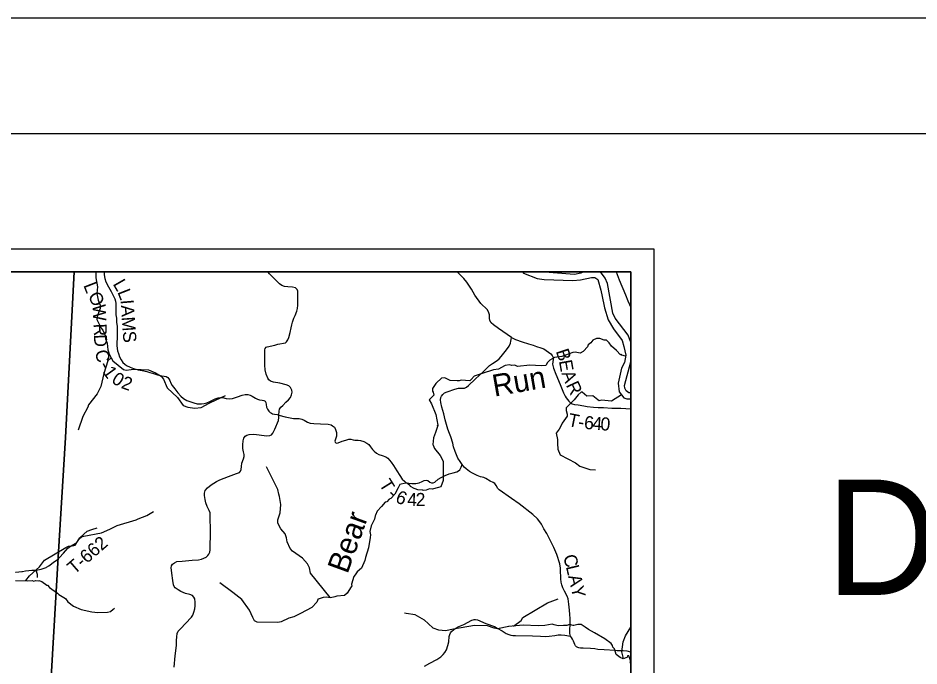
# Model space of a CAD drawing. Extents: x -1.8 to 75.7, y -2 to 25.
# Drawn here: x 47.944 to 51.85, y 20.804 to 23.612 of the extents above; entities that cross this region are included whole.
import ezdxf

# ---------------------------------------------------------------- set-up
doc = ezdxf.new("R2010")
doc.units = 0
for name, color, linetype in [('GM_X_County_Road', 7, 'Continuous'), ('GM_X_County_Road_Text', 7, 'Continuous'), ('GM_X_Major_River', 7, 'Continuous'), ('GM_X_Minor_River', 7, 'Continuous'), ('GM_X_Minor_River_Text', 7, 'Continuous'), ('GM_X_Township', 7, 'Continuous'), ('GM_X_Township_Road', 7, 'Continuous'), ('GM_X_Township_Road_Text', 7, 'Continuous'), ('GM_X_Township_ROW', 7, 'Continuous'), ('SH_Border', 7, 'Continuous'), ('SH_Cut_Line', 7, 'Continuous'), ('SH_Data', 7, 'Continuous'), ('SH_Text', 7, 'Continuous')]:
    doc.layers.add(name, color=color, linetype=linetype)

msp = doc.modelspace()

# ---------------------------------------------------------------- linework, layer by layer
at = {"layer": 'GM_X_County_Road'}
for points in [[(48.3169, 22.5121), (48.3169, 22.5118), (48.318, 22.4997), (48.3204, 22.4834), (48.3253, 22.4689), (48.3357, 22.4478), (48.348, 22.4269), (48.3566, 22.41), (48.363, 22.3958), (48.367, 22.3857), (48.3681, 22.3747), (48.3681, 22.3575), (48.3677, 22.341), (48.368, 22.3276), (48.3682, 22.3261)], [(48.6209, 20.7993), (48.6259, 20.8475), (48.6307, 20.8934), (48.6311, 20.9145), (48.6318, 20.9299), (48.6341, 20.9453), (48.6388, 20.9553), (48.6492, 20.9668), (48.6701, 20.9888), (48.6956, 21.0157), (48.7013, 21.0236), (48.7067, 21.0368), (48.7106, 21.0524), (48.7117, 21.0648), (48.7119, 21.0811), (48.7101, 21.0945), (48.7061, 21.1026), (48.7008, 21.1094), (48.6888, 21.1142), (48.6707, 21.1189), (48.6501, 21.1266), (48.6381, 21.1341), (48.6245, 21.1429), (48.6202, 21.1484), (48.618, 21.1556), (48.6146, 21.1744), (48.6101, 21.207), (48.6092, 21.2195), (48.6085, 21.229), (48.61, 21.2386), (48.6137, 21.2455), (48.6218, 21.2518), (48.632, 21.2564), (48.6549, 21.2586), (48.699, 21.2625), (48.7262, 21.2641), (48.7391, 21.2675), (48.7498, 21.2713), (48.7593, 21.2763), (48.7672, 21.2826), (48.7708, 21.2885), (48.7749, 21.2978), (48.7765, 21.3073), (48.7769, 21.3175), (48.7769, 21.3365), (48.7787, 21.361), (48.779, 21.3825), (48.7778, 21.4051), (48.7767, 21.4348), (48.7776, 21.4545), (48.7765, 21.4676), (48.7733, 21.4785), (48.7642, 21.4959), (48.7584, 21.5115), (48.7548, 21.5258), (48.7525, 21.5432), (48.7518, 21.5537), (48.755, 21.5647), (48.7647, 21.5761), (48.7819, 21.5892), (48.805, 21.6041), (48.8195, 21.6112), (48.8568, 21.6257), (48.8906, 21.6388), (48.9042, 21.6426), (48.9089, 21.649), (48.9112, 21.6562), (48.9123, 21.6691), (48.9148, 21.6834), (48.9214, 21.702), (48.9239, 21.7126), (48.9239, 21.721), (48.9216, 21.7327), (48.9193, 21.7459), (48.9189, 21.7629), (48.9196, 21.7803), (48.9223, 21.7914), (48.9282, 21.8002), (48.9352, 21.8041), (48.9463, 21.8072), (48.966, 21.8081), (49.023, 21.802), (49.0357, 21.8025), (49.0425, 21.8059), (49.0493, 21.8133), (49.058, 21.8301), (49.0725, 21.8684), (49.0747, 21.8803), (49.0744, 21.8912), (49.0757, 21.908), (49.0781, 21.9172), (49.0834, 21.9252), (49.0917, 21.9332), (49.1055, 21.9468), (49.1169, 21.9579), (49.1247, 21.9679), (49.13, 21.9785), (49.1322, 21.9904), (49.131, 22.0001), (49.1256, 22.0112), (49.1179, 22.0183), (49.1065, 22.0229), (49.0788, 22.029), (49.0514, 22.0338), (49.0388, 22.0387), (49.031, 22.044), (49.0264, 22.052), (49.0196, 22.0683), (49.0153, 22.087), (49.0142, 22.1083), (49.0136, 22.1418), (49.0136, 22.1646), (49.0136, 22.1738), (49.0157, 22.1796), (49.0196, 22.1852), (49.0245, 22.1874), (49.0567, 22.1942), (49.0703, 22.1988), (49.1033, 22.2051), (49.1082, 22.2092), (49.1133, 22.2174), (49.1181, 22.2281), (49.1234, 22.249), (49.1283, 22.2691), (49.1312, 22.2822), (49.1341, 22.2941), (49.1397, 22.3111), (49.1448, 22.3225), (49.153, 22.3411), (49.1557, 22.354), (49.1574, 22.3678), (49.1576, 22.3875), (49.1576, 22.4173), (49.1567, 22.4287), (49.1535, 22.436), (49.147, 22.443), (49.1341, 22.4457), (49.1133, 22.4474), (49.0987, 22.4486), (49.0875, 22.4534), (49.0776, 22.4605), (49.057, 22.4811), (49.0337, 22.5029), (49.0263, 22.5121)], [(50.313, 21.1285), (50.3057, 21.1432), (50.3016, 21.1562), (50.2992, 21.1671), (50.2976, 21.1819), (50.297, 21.1938), (50.2963, 21.211), (50.2963, 21.2279), (50.2932, 21.2472), (50.2806, 21.2868), (50.2672, 21.3177), (50.2547, 21.3435), (50.2459, 21.3613), (50.236, 21.3782), (50.2237, 21.3983), (50.2135, 21.418), (50.2067, 21.4293), (50.1967, 21.4418), (50.1758, 21.4604), (50.1164, 21.5067), (50.0831, 21.5305), (50.0305, 21.5672), (50.0236, 21.5739), (50.0169, 21.5864), (50.0111, 21.5944), (50.0033, 21.5994), (49.9915, 21.6053), (49.9727, 21.6159), (49.963, 21.6205), (49.9491, 21.6245), (49.9341, 21.6301), (49.9142, 21.6396), (49.9017, 21.6475), (49.8872, 21.6586), (49.8788, 21.6664), (49.87, 21.6772), (49.8614, 21.6902), (49.8511, 21.7053), (49.8446, 21.719), (49.8392, 21.7339), (49.832, 21.7538), (49.8297, 21.7704), (49.8208, 21.7968), (49.8147, 21.8111), (49.8078, 21.8299), (49.7955, 21.8714), (49.7897, 21.8974), (49.7819, 21.925), (49.7769, 21.9454), (49.7763, 21.9571), (49.7773, 21.967), (49.7797, 21.9733), (49.7856, 21.9813), (49.7925, 21.9875), (49.8052, 21.9925), (49.8374, 22.0031), (49.8535, 22.0074), (49.8686, 22.0074), (49.879, 22.0087), (49.888, 22.0122), (49.8965, 22.0191), (49.9253, 22.0464), (49.9637, 22.0823), (49.9758, 22.0941), (49.988, 22.1065), (50.0012, 22.1149), (50.0206, 22.1285), (50.0293, 22.135), (50.039, 22.1456), (50.0615, 22.1735), (50.0734, 22.1906), (50.0794, 22.2025), (50.0812, 22.2118), (50.0816, 22.2187), (50.0831, 22.2269), (50.0265, 22.266), (50.0059, 22.2818), (49.9948, 22.2915), (49.99, 22.302), (49.9883, 22.3108), (49.988, 22.3264), (49.9837, 22.3389), (49.9776, 22.3487), (49.9505, 22.3753), (49.9249, 22.4108), (49.9093, 22.4374), (49.8903, 22.4676), (49.8761, 22.4838), (49.8494, 22.5102), (49.8464, 22.5121)], [(50.5376, 22.5121), (50.5503, 22.4781), (50.577, 22.4131), (50.5878, 22.3872), (50.6002, 22.3575)], [(48.3682, 22.3261), (48.3703, 22.3108), (48.3715, 22.2941), (48.3732, 22.2752), (48.3739, 22.2582), (48.3741, 22.2393), (48.3736, 22.2237), (48.3727, 22.2067), (48.3727, 22.1926), (48.3739, 22.1806), (48.3758, 22.1697), (48.3791, 22.1586), (48.3845, 22.1442), (48.3911, 22.1312), (48.3984, 22.1197), (48.4064, 22.1121), (48.4147, 22.1064), (48.4296, 22.0987), (48.4452, 22.093), (48.465, 22.088), (48.482, 22.0847), (48.502, 22.08), (48.5148, 22.0765), (48.5273, 22.0732), (48.5355, 22.0706), (48.548, 22.0659), (48.5596, 22.0628), (48.5676, 22.0611), (48.578, 22.0607), (48.5865, 22.0583), (48.5934, 22.0536), (48.5976, 22.0486), (48.6019, 22.0406), (48.607, 22.029), (48.6122, 22.0198), (48.6238, 22.0047), (48.6368, 21.988), (48.6498, 21.9736), (48.662, 21.9634), (48.6764, 21.9547), (48.7066, 21.9438), (48.721, 21.9398), (48.739, 21.9396), (48.7515, 21.9415), (48.7628, 21.945), (48.7756, 21.9502), (48.7987, 21.9618), (48.8114, 21.9665), (48.8216, 21.9679), (48.8308, 21.9674), (48.8459, 21.9639), (48.861, 21.962), (48.874, 21.9634), (48.895, 21.97), (48.915, 21.9771), (48.9282, 21.9807), (48.9408, 21.9802), (48.9497, 21.9781), (48.9594, 21.9738), (48.9728, 21.9653), (48.9823, 21.9604), (48.991, 21.9578), (49.0021, 21.9566), (49.009, 21.9549), (49.0149, 21.9512), (49.0186, 21.9455), (49.0198, 21.937), (49.0212, 21.9254), (49.0255, 21.9167), (49.0318, 21.9082), (49.0371, 21.9029), (49.0434, 21.899), (49.0473, 21.8973), (49.0565, 21.8956), (49.0679, 21.8939), (49.0744, 21.8912)], [(50.3396, 20.9335), (50.3369, 20.9442), (50.3367, 20.957), (50.3373, 20.9879), (50.3373, 21.0099), (50.3365, 21.027), (50.3344, 21.0461), (50.3321, 21.0725), (50.3311, 21.0842), (50.3286, 21.0955), (50.3241, 21.1066), (50.3131, 21.1283), (50.313, 21.1285)], [(50.6002, 20.864), (50.5856, 20.8677), (50.5674, 20.8693), (50.5419, 20.8704), (50.5325, 20.8709), (50.4847, 20.8735), (50.458, 20.876), (50.4449, 20.8777), (50.4261, 20.8796), (50.3937, 20.8816), (50.3828, 20.8819), (50.3752, 20.8825), (50.3705, 20.8841), (50.3654, 20.887), (50.3604, 20.8918), (50.3574, 20.8979), (50.352, 20.9113), (50.3481, 20.9197), (50.343, 20.9273), (50.3396, 20.9335)]]:
    msp.add_lwpolyline(points, dxfattribs=at)
at = {"layer": 'GM_X_Major_River'}
msp.add_line((50.5792, 22.1512), (50.5733, 22.119), dxfattribs=at)
for points in [[(50.1307, 22.5121), (50.1359, 22.5067), (50.195, 22.4832), (50.2245, 22.4788), (50.3494, 22.4742)], [(50.3966, 22.5121), (50.3836, 22.5071), (50.3564, 22.5001), (50.2637, 22.5075), (50.2139, 22.5121)], [(50.6002, 22.2099), (50.6, 22.2105), (50.5889, 22.2374), (50.5333, 22.3111), (50.5226, 22.3326), (50.4999, 22.4618), (50.49, 22.4842), (50.474, 22.5061), (50.4641, 22.5121)], [(50.3494, 22.4742), (50.383, 22.4771), (50.4306, 22.488), (50.445, 22.4881), (50.4575, 22.4791), (50.471, 22.4332), (50.4842, 22.3703), (50.4873, 22.3563), (50.5027, 22.3037), (50.5256, 22.2647), (50.5629, 22.2141), (50.5703, 22.1884), (50.5792, 22.1512)], [(50.5733, 22.119), (50.5602, 22.095), (50.5462, 22.0293), (50.5509, 21.9921), (50.57, 21.9664), (50.5828, 21.9612), (50.5957, 21.9617), (50.6002, 21.9621)], [(50.6002, 21.9872), (50.5918, 21.9874), (50.5811, 21.9965), (50.575, 22.0078), (50.5734, 22.0199), (50.6002, 22.1222)]]:
    msp.add_lwpolyline(points, dxfattribs=at)
at = {"layer": 'GM_X_Minor_River'}
for points in [[(48.2818, 22.5121), (48.2811, 22.4867), (48.2885, 22.4466), (48.285, 22.4179), (48.2917, 22.3892), (48.2994, 22.3677), (48.2997, 22.3536), (48.2878, 22.3236), (48.2861, 22.305), (48.3043, 22.2676), (48.3112, 22.2594), (48.3229, 22.234), (48.3229, 22.2218), (48.3303, 22.2026), (48.3332, 22.1737), (48.3381, 22.1614), (48.3391, 22.1553), (48.3552, 22.1263), (48.4017, 22.0883), (48.4129, 22.0857), (48.4338, 22.0884), (48.4475, 22.091), (48.5097, 22.0871), (48.5396, 22.0752), (48.5645, 22.0603), (48.5739, 22.0464), (48.5901, 22.009), (48.6346, 21.967), (48.6593, 21.9335), (48.6806, 21.9252), (48.7111, 21.9208), (48.7384, 21.9245), (48.773, 21.9432), (48.7784, 21.9464), (48.8432, 21.9762)], [(50.5782, 22.1461), (50.5617, 22.1509), (50.5583, 22.1547), (50.5564, 22.1528), (50.5386, 22.1714), (50.5174, 22.1899), (50.5065, 22.2051), (50.4959, 22.2157), (50.4845, 22.2157), (50.466, 22.2233), (50.4524, 22.2228), (50.4365, 22.2156), (50.4271, 22.2045), (50.4154, 22.1958), (50.4131, 22.1874), (50.3957, 22.1691), (50.3942, 22.1672), (50.3806, 22.16), (50.3598, 22.1637), (50.3492, 22.1622), (50.3012, 22.1457), (50.2699, 22.1403), (50.2498, 22.13), (50.2389, 22.1186), (50.2321, 22.1057), (50.2117, 22.1052), (50.1633, 22.1074), (50.11, 22.1019), (50.0983, 22.1076), (50.0843, 22.1068), (50.0752, 22.1095), (50.0559, 22.106), (50.0525, 22.1052), (50.0268, 22.0907), (50.0061, 22.0873), (49.9562, 22.0719), (49.921, 22.0601), (49.9089, 22.046), (49.9033, 22.0399), (49.8655, 22.0432), (49.8564, 22.0394), (49.8477, 22.0401), (49.8175, 22.0412), (49.794, 22.0526), (49.7796, 22.0518), (49.7574, 22.0304), (49.7547, 22.0289), (49.7408, 22.0068), (49.7411, 21.9954), (49.7442, 21.9913), (49.7461, 21.9776), (49.7264, 21.957), (49.7359, 21.9399), (49.7548, 21.8944), (49.764, 21.8484), (49.7606, 21.8446), (49.764, 21.8457), (49.7545, 21.8153), (49.7455, 21.7928), (49.7429, 21.7636), (49.7433, 21.7613), (49.7497, 21.7461), (49.7739, 21.7169), (49.7868, 21.6922), (49.7868, 21.6675), (49.7865, 21.6185), (49.7872, 21.6075), (49.7771, 21.5804), (49.7676, 21.577), (49.7393, 21.5709), (49.7276, 21.5716), (49.7128, 21.5666), (49.7003, 21.5639), (49.6988, 21.5666), (49.6777, 21.5673), (49.6659, 21.5722), (49.661, 21.5726), (49.6451, 21.5813), (49.6448, 21.5851), (49.6323, 21.5949), (49.6236, 21.5968), (49.5998, 21.5899), (49.5915, 21.5762), (49.5779, 21.5484), (49.5601, 21.5302), (49.5537, 21.5275), (49.5424, 21.5157), (49.5359, 21.5138), (49.5193, 21.4955), (49.5016, 21.4745), (49.4933, 21.457), (49.4925, 21.4547), (49.4895, 21.4407), (49.4744, 21.4117), (49.4699, 21.387), (49.4726, 21.373), (49.4711, 21.3604), (49.4632, 21.3163), (49.45, 21.2748), (49.4477, 21.2608), (49.433, 21.2284)], [(48.3461, 22.1387), (48.3336, 22.1266), (48.3153, 22.071), (48.303, 22.0148), (48.287, 21.9841), (48.2493, 21.9364), (48.247, 21.9258), (48.2243, 21.8851), (48.2043, 21.8262)], [(50.5608, 21.9788), (50.5169, 21.9512), (50.474, 21.9564), (50.4633, 21.9537), (50.4581, 21.9569), (50.4356, 21.9747), (50.4106, 21.974), (50.3904, 21.9906), (50.3854, 21.99), (50.3723, 21.9794), (50.3549, 21.9568), (50.321, 21.9229), (50.3203, 21.9119), (50.3255, 21.8947), (50.3241, 21.8871), (50.3035, 21.8567), (50.3011, 21.8514), (50.2906, 21.8309), (50.2765, 21.8135), (50.2828, 21.7855), (50.2827, 21.7677), (50.2838, 21.7437), (50.294, 21.7187), (50.3607, 21.6843), (50.3795, 21.6704), (50.4237, 21.6561), (50.4474, 21.6538)], [(49.2966, 21.1009), (49.2113, 21.2058), (49.2071, 21.2298), (49.1985, 21.2464), (49.1777, 21.271), (49.1344, 21.302), (49.1231, 21.3138), (49.1103, 21.3415), (49.1086, 21.3594), (49.1019, 21.3764), (49.0829, 21.3979), (49.0704, 21.4226), (49.0705, 21.437), (49.0801, 21.4674), (49.0831, 21.5042), (49.0774, 21.5389), (49.075, 21.5493), (49.0707, 21.5695), (49.0247, 21.661), (49.0215, 21.6675)], [(47.9775, 21.1747), (47.9936, 21.1945), (48.0363, 21.2342), (48.0591, 21.2631), (48.1515, 21.3182), (48.1623, 21.3232), (48.1732, 21.3228), (48.1919, 21.3283), (48.209, 21.3551), (48.2198, 21.3643), (48.2294, 21.367), (48.3061, 21.3813), (48.3421, 21.3964), (48.3733, 21.4129), (48.456, 21.438), (48.4652, 21.4411), (48.5019, 21.4559), (48.5312, 21.4732)], [(49.433, 21.2284), (49.4141, 21.2124), (49.4058, 21.1987), (49.3998, 21.1926), (49.3896, 21.1584), (49.3915, 21.1489), (49.3892, 21.1485), (49.3889, 21.1466), (49.3707, 21.1192), (49.3587, 21.11), (49.3265, 21.1073), (49.3171, 21.1031), (49.2986, 21.0996), (49.2793, 21.1026), (49.2664, 21.1007), (49.2449, 21.0942)], [(47.9334, 21.1752), (47.9845, 21.1734), (48.0045, 21.1746), (48.0124, 21.1719), (48.0196, 21.175), (48.031, 21.1727), (48.034, 21.1747), (48.0465, 21.1697), (48.0684, 21.155), (48.0718, 21.1542), (48.0805, 21.1444), (48.1152, 21.1192)], [(49.2456, 21.0944), (49.239, 21.0803), (49.2183, 21.0574), (49.168, 21.0321), (49.1396, 21.017), (49.1186, 21.0112), (49.0845, 20.9949), (49.0708, 20.993), (48.9808, 20.9936), (48.9697, 21.0004), (48.9622, 21.0136), (48.9477, 21.0467), (48.9147, 21.0922), (48.8759, 21.1227), (48.8189, 21.164)], [(48.115, 21.1194), (48.1214, 21.1137), (48.1494, 21.0962), (48.1603, 21.0814), (48.1846, 21.0629), (48.2175, 21.0485), (48.264, 21.0387), (48.29, 21.0361), (48.332, 21.0374), (48.3452, 21.0408), (48.3566, 21.05), (48.36, 21.0526), (48.3626, 21.0553)], [(50.0922, 20.9773), (50.126, 21.0018), (50.1332, 21.0145), (50.2391, 21.078), (50.286, 21.0951)], [(50.0715, 20.9757), (50.0229, 20.9656), (50.0078, 20.9676), (49.9794, 20.978), (49.9224, 20.9798), (49.8316, 20.9634), (49.7966, 20.9558), (49.7679, 20.9597), (49.7433, 20.9685), (49.7227, 20.9889), (49.7065, 21.0027), (49.6652, 21.0253), (49.6261, 21.0318), (49.6202, 21.0324)], [(50.6002, 20.817), (50.5981, 20.8176), (50.5989, 20.8206), (50.5992, 20.8282), (50.5917, 20.8483), (50.5867, 20.8476), (50.5849, 20.843), (50.5834, 20.8403), (50.5679, 20.8353), (50.5539, 20.8414), (50.5372, 20.8543), (50.5296, 20.8782), (50.5221, 20.8858), (50.5217, 20.8923), (50.5149, 20.9017), (50.4884, 20.9211), (50.4434, 20.9483), (50.4169, 20.9616), (50.4033, 20.9722), (50.3851, 20.9836), (50.3715, 20.9835), (50.3541, 20.9789), (50.3515, 20.9797), (50.3352, 20.9834), (50.3235, 20.9792), (50.3088, 20.98), (50.2857, 20.978), (50.2683, 20.9821), (50.2604, 20.9855), (50.2275, 20.979), (50.1984, 20.9786), (50.1337, 20.9807), (50.0709, 20.9756)], [(50.5695, 20.8359), (50.5615, 20.8656), (50.5674, 20.9087), (50.5772, 20.935), (50.6002, 20.9716)]]:
    msp.add_lwpolyline(points, dxfattribs=at)
at = {"layer": 'GM_X_Township'}
for points in [[(48.1876, 22.5121), (43.8002, 22.5121), (43.8002, 18.978)], [(43.8002, 18.978), (44.8356, 18.9224), (45.3865, 18.8952), (46.1197, 18.859), (46.3714, 18.8466), (46.9192, 18.8195), (47.1815, 18.806), (47.9522, 18.7663), (48.0201, 19.5982), (48.0214, 19.6198), (48.0228, 19.6698), (48.0235, 19.6926), (48.0261, 19.7186), (48.0301, 19.7636), (48.0891, 20.7799), (48.1186, 21.2763), (48.1494, 21.7937), (48.1876, 22.5121)], [(48.1876, 22.5121), (48.1494, 21.7937), (48.1186, 21.2763), (48.0891, 20.7799), (48.0301, 19.7636), (48.0261, 19.7186), (48.0235, 19.6926), (48.0228, 19.6698), (48.0214, 19.6198), (48.0201, 19.5982), (47.9522, 18.7663), (48.8964, 18.7242), (49.0051, 18.7193), (50.1896, 18.6602), (50.591, 18.6401), (50.6002, 18.6397)], [(50.6002, 18.6397), (50.6002, 22.5121), (48.1876, 22.5121)]]:
    msp.add_lwpolyline(points, dxfattribs=at)
at = {"layer": 'GM_X_Township_Road'}
for points in [[(50.0831, 22.2269), (50.1004, 22.2194), (50.1302, 22.2088), (50.1566, 22.1999), (50.1767, 22.1938), (50.1923, 22.1891), (50.2109, 22.1822), (50.223, 22.1781), (50.2336, 22.1714), (50.2544, 22.1566), (50.2595, 22.1499), (50.2637, 22.1409), (50.2645, 22.1329), (50.2628, 22.1216), (50.2613, 22.1127), (50.2622, 22.1056), (50.2649, 22.0942), (50.2752, 22.0685), (50.2944, 22.0236), (50.3089, 21.9875), (50.316, 21.9733), (50.3205, 21.9655), (50.3257, 21.9588), (50.332, 21.9516), (50.3378, 21.946), (50.346, 21.9408), (50.3568, 21.9378), (50.3724, 21.9352), (50.3975, 21.9312)], [(50.3975, 21.9312), (50.4122, 21.9289), (50.4393, 21.9263), (50.4593, 21.9246), (50.4818, 21.9237), (50.518, 21.9216), (50.5582, 21.9209), (50.6002, 21.9188)], [(49.0744, 21.8912), (49.1026, 21.8839), (49.138, 21.8769), (49.1632, 21.8759), (49.1749, 21.874), (49.1849, 21.8696), (49.1986, 21.8603), (49.2099, 21.8566), (49.227, 21.8546), (49.2549, 21.8541), (49.2892, 21.8515), (49.301, 21.849), (49.3079, 21.8454), (49.3156, 21.8386), (49.3207, 21.8296), (49.3249, 21.8156), (49.3245, 21.8003), (49.3205, 21.7866), (49.318, 21.7782), (49.3191, 21.7737), (49.3236, 21.77), (49.332, 21.7709), (49.3497, 21.7782), (49.365, 21.7828), (49.3785, 21.7874), (49.3874, 21.7872), (49.3967, 21.7841), (49.4044, 21.7826), (49.4186, 21.783), (49.4294, 21.7815), (49.443, 21.7768), (49.456, 21.77), (49.4642, 21.7644), (49.4724, 21.7536), (49.4808, 21.7429), (49.4879, 21.735), (49.4981, 21.7268), (49.5085, 21.7212), (49.5227, 21.7161), (49.5382, 21.7106), (49.5466, 21.7051), (49.5617, 21.6878), (49.5719, 21.6734), (49.5866, 21.6504), (49.5998, 21.6295), (49.6093, 21.6136), (49.6188, 21.6043), (49.6255, 21.5994), (49.6381, 21.5959), (49.6512, 21.5948), (49.6684, 21.5943), (49.6833, 21.5983), (49.6961, 21.6034), (49.7043, 21.6076), (49.713, 21.6089), (49.7203, 21.6074), (49.7296, 21.6014), (49.7371, 21.5979), (49.7431, 21.5974), (49.7506, 21.6014), (49.7655, 21.6136), (49.7781, 21.6209), (49.7954, 21.6298), (49.8126, 21.6366), (49.8312, 21.6411), (49.8467, 21.6455), (49.8538, 21.6493), (49.8594, 21.6537), (49.8649, 21.6652), (49.87, 21.6772)], [(48.0672, 21.232), (48.0777, 21.2388), (48.1023, 21.2564), (48.1129, 21.2637), (48.1182, 21.2685), (48.1241, 21.274), (48.1414, 21.2933), (48.1598, 21.3142), (48.1721, 21.3231), (48.1947, 21.3362), (48.202, 21.3441), (48.2117, 21.3589), (48.2285, 21.3759), (48.2438, 21.3879), (48.2634, 21.3949), (48.2863, 21.403)], [(47.933, 21.2107), (47.9345, 21.2109), (47.9597, 21.2138)], [(47.9597, 21.2138), (47.9633, 21.2142), (47.9767, 21.2165), (47.9906, 21.2179), (48.0035, 21.2187), (48.0222, 21.2187)], [(48.0222, 21.2187), (48.0448, 21.2235), (48.0657, 21.231), (48.0672, 21.232)], [(49.706, 20.8032), (49.7287, 20.8161), (49.7603, 20.8322), (49.7766, 20.8444), (49.7873, 20.8534), (49.7949, 20.8628), (49.8019, 20.8747), (49.8078, 20.8923), (49.8112, 20.9091), (49.8137, 20.9315), (49.8162, 20.94), (49.8192, 20.948), (49.8235, 20.954), (49.8332, 20.9616), (49.8426, 20.9683), (49.8552, 20.9747), (49.8767, 20.9843), (49.9115, 21.0024), (49.9169, 21.0047), (49.9216, 21.0056), (49.9272, 21.0056), (49.9361, 21.0036), (49.9727, 20.9885), (50.0096, 20.9745), (50.0214, 20.9685), (50.0425, 20.9563), (50.0604, 20.9453), (50.0714, 20.9406), (50.0801, 20.938), (50.0893, 20.9368), (50.1007, 20.9358), (50.1748, 20.9346), (50.2096, 20.9327), (50.2295, 20.9324), (50.2468, 20.9329), (50.2712, 20.9363), (50.2856, 20.9385), (50.2992, 20.9391), (50.3144, 20.9372), (50.3396, 20.9335)]]:
    msp.add_lwpolyline(points, dxfattribs=at)
at = {"layer": 'GM_X_Township_ROW'}
msp.add_lwpolyline([(48.0286, 21.188), (48.028, 21.2008), (48.0222, 21.2187)], dxfattribs=at)
at = {"layer": 'SH_Border'}
msp.add_lwpolyline([(43.2002, 23.1121), (75.2002, 23.1121), (75.2002, 2.1121), (43.2002, 2.1121)], close=True, dxfattribs=at)
at = {"layer": 'SH_Cut_Line'}
msp.add_lwpolyline([(41.7002, 1.6121), (75.7002, 1.6121), (75.7002, 23.6121), (41.7002, 23.6121)], close=True, dxfattribs=at)
at = {"layer": 'SH_Data'}
for p, q in [((43.7002, 22.6121), (50.7002, 22.6121)), ((50.7002, 22.6121), (50.7002, 15.6121)), ((43.8002, 22.5121), (50.6002, 22.5121)), ((43.8002, 22.5121), (50.6002, 22.5121)), ((50.6002, 22.5121), (50.6002, 15.7121)), ((50.6002, 22.5121), (50.6002, 15.7121))]:
    msp.add_line(p, q, dxfattribs=at)

# ---------------------------------------------------------------- texts
at = {"layer": 'GM_X_County_Road_Text'}
for s, rotation, p in [('L', 291.2729, (48.2265, 22.4543)), ('L', 299.8274, (48.3536, 22.4599)), ('O', 298.5018, (48.2452, 22.4076)), ('L', 291.4457, (48.3738, 22.425)), ('I', 274.7828, (48.3884, 22.3897)), ('W', 272.4964, (48.2672, 22.3701)), ('A', 273.1818, (48.3903, 22.3668)), ('M', 273.9872, (48.3931, 22.316)), ('R', 272.303, (48.2708, 22.2868)), ('D', 272.4218, (48.2727, 22.2401)), ('S', 275.1606, (48.3975, 22.2533)), ('C', 282.5703, (48.277, 22.168)), ('-', 296.9471, (48.2924, 22.1078)), ('1', 305.93, (48.3081, 22.0787)), ('0', 327.6164, (48.3456, 22.0344)), ('2', 340.2531, (48.3875, 22.0096)), ('C', 284.8811, (50.3068, 21.2795)), ('L', 283.4116, (50.3187, 21.2347)), ('A', 283.2649, (50.3285, 21.1934)), ('Y', 282.2601, (50.3399, 21.145))]:
    msp.add_text(s, height=0.0568, rotation=rotation, dxfattribs=at).set_placement(p)
at = {"layer": 'GM_X_Minor_River_Text'}
for s, rotation, p in [('Run', 9.9969, (50.0089, 21.9711)), ('Bear', 69.9999, (49.372, 21.1998))]:
    msp.add_text(s, height=0.0947, rotation=rotation, dxfattribs=at).set_placement(p)
at = {"layer": 'GM_X_Township_Road_Text'}
for s, height, rotation, p in [('B', 0.0568, 288.0968, (50.2749, 22.1683)), ('E', 0.0568, 280.0193, (50.2888, 22.126)), ('A', 0.0568, 290.6476, (50.2993, 22.0731)), ('R', 0.0568, 294.8309, (50.3187, 22.0221)), ('T', 0.0568, 348.6048, (50.3252, 21.8447)), ('6', 0.0568, 354.6585, (50.3964, 21.8319)), ('4', 0.0568, 355.9016, (50.4326, 21.8285)), ('0', 0.0568, 356.0397, (50.4676, 21.826)), ('-', 0.0568, 351.4113, (50.3698, 21.8358)), ('T', 0.0568, 301.8153, (49.5075, 21.5918)), ('6', 0.0568, 337.7004, (49.5764, 21.5154)), ('-', 0.0568, 317.7887, (49.541, 21.5425)), ('4', 0.0568, 358.6796, (49.6308, 21.4975)), ('2', 0.0568, 1.2166, (49.6686, 21.4967)), ('T-662', 0.05682, 40.9289, (48.1881, 21.1989))]:
    msp.add_text(s, height=height, rotation=rotation, dxfattribs=at).set_placement(p)
at = {"layer": 'SH_Text'}
msp.add_text('DEPARTMENT OF TRANSPORTATION', height=0.5, dxfattribs=at).set_placement((51.4468, 21.1121))

doc.saveas('drawing.dxf')
